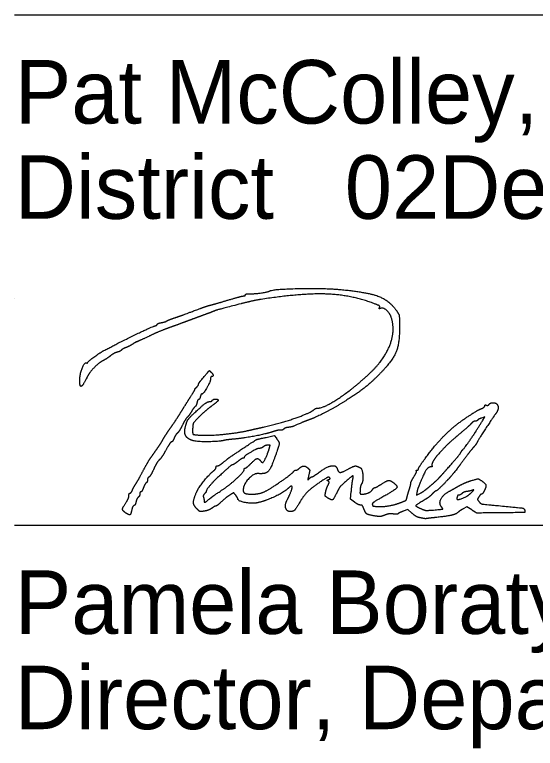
# Model space of a CAD drawing. Extents: x 0 to 34, y 0 to 22.
# Drawn here: x 24.5 to 25.648, y 7.199 to 8.816 of the extents above; entities that cross this region are included whole.
import ezdxf

# ---------------------------------------------------------------- set-up
doc = ezdxf.new("R2010")
doc.units = 0
doc.layers.add('SH_Data', color=7, linetype='Continuous')
doc.layers.add('SH_Text', color=7, linetype='Continuous')

msp = doc.modelspace()

# ---------------------------------------------------------------- linework, layer by layer
at = {"layer": 'SH_Data'}
for p, q in [((24.5, 8.816), (28, 8.816)), ((24.5, 8.191), (24.5, 8.191)), ((24.5, 7.691), (28, 7.691))]:
    msp.add_line(p, q, dxfattribs=at)
at = {"layer": 'SH_Text'}
for points in [[(25.5318, 7.9205), (25.5372, 7.9294), (25.5298, 7.9268)], [(25.0545, 7.8843), (25.0725, 7.8883), (25.0772, 7.8822)], [(25.2494, 7.7415), (25.2411, 7.7478), (25.2426, 7.7649)], [(25.3874, 7.7635), (25.3864, 7.757), (25.3951, 7.7614)], [(25.5083, 7.7242), (25.4976, 7.731), (25.4892, 7.7264)], [(25.3764, 7.7172), (25.3672, 7.7254), (25.3567, 7.7214)]]:
    msp.add_lwpolyline(points, dxfattribs=at)
for points in [[(25.0089, 8.1984), (25.0089, 8.1998), (25.0129, 8.2008), (25.0179, 8.2007)], [(25.0179, 8.2007), (25.0275, 8.2004), (25.0585, 8.2047), (25.0619, 8.2069)], [(25.2926, 8.1792), (25.242, 8.1982), (25.1341, 8.2022), (25.0437, 8.1884)], [(25.0619, 8.2069), (25.0687, 8.2111), (25.1857, 8.2134), (25.2201, 8.21)], [(25.2201, 8.21), (25.2794, 8.2041), (25.3269, 8.1858), (25.3427, 8.1628)], [(24.9333, 8.1761), (24.9386, 8.1775), (24.9561, 8.1825), (24.9721, 8.1873)], [(24.9721, 8.1873), (24.9882, 8.192), (25.0031, 8.1959), (25.0051, 8.1959)], [(25.0437, 8.1884), (25.0345, 8.187), (25.0145, 8.1827), (24.9993, 8.1787)], [(25.0051, 8.1959), (25.0072, 8.1959), (25.0089, 8.1971), (25.0089, 8.1984)], [(24.8529, 8.1477), (24.8676, 8.1528), (24.8741, 8.1552), (24.9093, 8.1683)], [(24.9093, 8.1683), (24.9172, 8.1713), (24.928, 8.1748), (24.9333, 8.1761)], [(24.9993, 8.1787), (24.9483, 8.1655), (24.944, 8.1643), (24.9333, 8.1599)], [(25.3049, 8.1706), (25.3059, 8.1731), (25.3024, 8.1755), (25.2926, 8.1792)], [(25.3073, 8.1685), (25.3047, 8.1675), (25.304, 8.1682), (25.3049, 8.1706)], [(25.3307, 8.1486), (25.3274, 8.1584), (25.313, 8.1707), (25.3073, 8.1685)], [(24.9105, 8.1515), (24.9006, 8.1479), (24.8855, 8.1423), (24.8769, 8.1391)], [(24.9333, 8.1599), (24.9307, 8.1589), (24.9204, 8.1551), (24.9105, 8.1515)], [(25.3427, 8.1628), (25.3476, 8.1555), (25.3486, 8.1512), (25.3489, 8.1333)], [(24.8145, 8.1334), (24.8145, 8.1345), (24.8185, 8.1362), (24.8235, 8.1371)], [(24.8235, 8.1371), (24.8284, 8.138), (24.8336, 8.1396), (24.8349, 8.1405)], [(24.8349, 8.1405), (24.8362, 8.1415), (24.8443, 8.1448), (24.8529, 8.1477)], [(24.8769, 8.1391), (24.8683, 8.1358), (24.8521, 8.1299), (24.8409, 8.1259)], [(25.2852, 8.0274), (25.3161, 8.0568), (25.34, 8.1204), (25.3307, 8.1486)], [(24.6969, 8.0755), (24.7271, 8.0918), (24.8007, 8.1274), (24.8091, 8.1299)], [(24.8409, 8.1259), (24.8297, 8.1219), (24.8093, 8.1134), (24.7957, 8.1069)], [(24.8091, 8.1299), (24.8121, 8.1308), (24.8145, 8.1324), (24.8145, 8.1334)], [(25.3489, 8.1333), (25.3496, 8.0926), (25.3335, 8.0529), (25.3041, 8.023)], [(24.7957, 8.1069), (24.782, 8.1004), (24.7704, 8.0951), (24.7698, 8.0951)], [(24.7598, 8.0895), (24.7549, 8.0864), (24.7482, 8.083), (24.745, 8.082)], [(24.7698, 8.0951), (24.7693, 8.0951), (24.7648, 8.0926), (24.7598, 8.0895)], [(24.6609, 8.0489), (24.6609, 8.0511), (24.6863, 8.0698), (24.6969, 8.0755)], [(24.7261, 8.072), (24.7226, 8.0711), (24.7159, 8.0675), (24.7113, 8.0639)], [(24.7358, 8.0768), (24.734, 8.075), (24.7297, 8.0728), (24.7261, 8.072)], [(24.745, 8.082), (24.7418, 8.0809), (24.7376, 8.0786), (24.7358, 8.0768)], [(24.7113, 8.0639), (24.7067, 8.0603), (24.6995, 8.0557), (24.6954, 8.0536)], [(24.6437, 8.0111), (24.6438, 8.0242), (24.6545, 8.0508), (24.6586, 8.0483)], [(24.6586, 8.0483), (24.6599, 8.0475), (24.6609, 8.0478), (24.6609, 8.0489)], [(24.6954, 8.0536), (24.685, 8.0482), (24.6651, 8.0274), (24.6589, 8.0153)], [(24.9111, 8.01), (24.9296, 8.0321), (24.9289, 8.0316), (24.933, 8.0282)], [(24.933, 8.0282), (24.9373, 8.0246), (24.9382, 8.0183), (24.9345, 8.0183)], [(25.1685, 7.9487), (25.1826, 7.9487), (25.2507, 7.9946), (25.2852, 8.0274)], [(25.3041, 8.023), (25.2855, 8.0041), (25.2531, 7.9792), (25.2226, 7.9603)], [(24.6451, 7.9973), (24.6443, 7.9981), (24.6437, 8.0043), (24.6437, 8.0111)], [(24.6589, 8.0153), (24.6522, 8.0024), (24.6469, 7.9955), (24.6451, 7.9973)], [(24.9057, 8.0013), (24.9057, 8.0025), (24.9081, 8.0064), (24.9111, 8.01)], [(24.9321, 8.0133), (24.9321, 8.0077), (24.9162, 7.9799), (24.913, 7.9799)], [(24.9345, 8.0183), (24.9332, 8.0183), (24.9321, 8.0161), (24.9321, 8.0133)], [(24.8881, 7.9739), (24.8937, 7.9825), (24.8977, 7.9895), (24.8971, 7.9895)], [(24.8971, 7.9895), (24.8966, 7.9895), (24.8983, 7.9917), (24.9009, 7.9943)], [(24.9009, 7.9943), (24.9035, 7.997), (24.9057, 8.0001), (24.9057, 8.0013)], [(24.8661, 7.9389), (24.8727, 7.9495), (24.8826, 7.9653), (24.8881, 7.9739)], [(24.9095, 7.9739), (24.9087, 7.9706), (24.907, 7.9679), (24.9058, 7.9679)], [(24.913, 7.9799), (24.9119, 7.9799), (24.9103, 7.9772), (24.9095, 7.9739)], [(24.8973, 7.939), (24.913, 7.9536), (24.9258, 7.9631), (24.9297, 7.9631)], [(24.9021, 7.9608), (24.9012, 7.9568), (24.8995, 7.953), (24.8982, 7.9522)], [(24.9058, 7.9679), (24.9047, 7.9679), (24.903, 7.9647), (24.9021, 7.9608)], [(24.9297, 7.9631), (24.9322, 7.9631), (24.9349, 7.9642), (24.9357, 7.9655)], [(24.9489, 7.9659), (24.9489, 7.9648), (24.9421, 7.9589), (24.9339, 7.9528)], [(24.9357, 7.9655), (24.9375, 7.9684), (24.9489, 7.9688), (24.9489, 7.9659)], [(25.2226, 7.9603), (25.2035, 7.9485), (25.1622, 7.9275), (25.1481, 7.9224)], [(25.5403, 7.9551), (25.5422, 7.9544), (25.545, 7.9554), (25.5466, 7.9573)], [(25.5466, 7.9573), (25.5482, 7.9592), (25.5519, 7.9607), (25.5548, 7.9607)], [(25.5548, 7.9607), (25.5643, 7.9607), (25.568, 7.9447), (25.5606, 7.9357)], [(24.8897, 7.9407), (24.8863, 7.9352), (24.8822, 7.9296), (24.8806, 7.9283)], [(24.8982, 7.9522), (24.8969, 7.9514), (24.8931, 7.9462), (24.8897, 7.9407)], [(24.9339, 7.9528), (24.9256, 7.9467), (24.9131, 7.9358), (24.9061, 7.9287)], [(25.0485, 7.9068), (25.0854, 7.915), (25.1517, 7.9379), (25.1603, 7.9454)], [(25.1603, 7.9454), (25.1624, 7.9472), (25.1661, 7.9487), (25.1685, 7.9487)], [(25.5001, 7.9304), (25.5191, 7.9426), (25.5209, 7.9437), (25.5291, 7.9474)], [(25.5291, 7.9474), (25.5334, 7.9493), (25.5369, 7.9521), (25.5369, 7.9537)], [(25.5369, 7.9537), (25.5369, 7.9552), (25.5384, 7.9559), (25.5403, 7.9551)], [(24.8443, 7.9059), (24.8497, 7.9134), (24.8595, 7.9282), (24.8661, 7.9389)], [(24.8806, 7.9283), (24.8789, 7.927), (24.8742, 7.9194), (24.8702, 7.9114)], [(24.876, 7.9043), (24.8787, 7.9174), (24.8849, 7.9274), (24.8973, 7.939)], [(24.9061, 7.9287), (24.8954, 7.9177), (24.8932, 7.914), (24.8927, 7.9058)], [(25.4055, 7.8378), (25.4278, 7.8686), (25.4728, 7.9127), (25.5001, 7.9304)], [(25.5606, 7.9357), (25.5564, 7.9307), (25.5236, 7.8802), (25.5204, 7.8741)], [(25.5298, 7.9268), (25.5258, 7.9254), (25.5219, 7.9233), (25.5212, 7.9221)], [(24.8702, 7.9114), (24.8662, 7.9034), (24.8611, 7.8954), (24.859, 7.8936)], [(25.1325, 7.9162), (25.1154, 7.9088), (25.1105, 7.9071), (25.1039, 7.9063)], [(25.1481, 7.9224), (25.1435, 7.9207), (25.1364, 7.918), (25.1325, 7.9162)], [(25.507, 7.9145), (25.5043, 7.9116), (25.4918, 7.9005), (25.4793, 7.89)], [(25.489, 7.8575), (25.4918, 7.8595), (25.52, 7.901), (25.5318, 7.9205)], [(25.5158, 7.9199), (25.5136, 7.9199), (25.5097, 7.9175), (25.507, 7.9145)], [(25.5212, 7.9221), (25.5204, 7.9209), (25.518, 7.9199), (25.5158, 7.9199)], [(24.8276, 7.8803), (24.8315, 7.8869), (24.839, 7.8985), (24.8443, 7.9059)], [(24.859, 7.8936), (24.8568, 7.8918), (24.8535, 7.8867), (24.8517, 7.8823)], [(24.8913, 7.8775), (24.8809, 7.8814), (24.8737, 7.8938), (24.876, 7.9043)], [(24.8927, 7.9058), (24.8918, 7.8923), (24.8959, 7.8895), (24.9165, 7.8889)], [(24.9165, 7.8889), (24.9358, 7.8884), (24.9936, 7.8945), (25.0149, 7.8993)], [(25.0683, 7.8963), (25.0518, 7.891), (25.0067, 7.8826), (24.9829, 7.8803)], [(25.0149, 7.8993), (25.0228, 7.9011), (25.0379, 7.9045), (25.0485, 7.9068)], [(25.0863, 7.9001), (25.0846, 7.9007), (25.0765, 7.899), (25.0683, 7.8963)], [(25.0931, 7.9022), (25.091, 7.9004), (25.0879, 7.8995), (25.0863, 7.9001)], [(25.1039, 7.9063), (25.1, 7.9059), (25.0952, 7.9041), (25.0931, 7.9022)], [(24.8146, 7.8597), (24.8179, 7.8645), (24.8238, 7.8737), (24.8276, 7.8803)], [(24.8517, 7.8823), (24.8498, 7.8779), (24.8473, 7.8743), (24.846, 7.8743)], [(24.9625, 7.8776), (24.9488, 7.8746), (24.8993, 7.8745), (24.8913, 7.8775)], [(24.9829, 7.8803), (24.9746, 7.8795), (24.9654, 7.8783), (24.9625, 7.8776)], [(25.0005, 7.8579), (25.0322, 7.8789), (25.0335, 7.8796), (25.0545, 7.8843)], [(25.0772, 7.8822), (25.0838, 7.8734), (25.0836, 7.8685), (25.0759, 7.846)], [(25.4793, 7.89), (25.4597, 7.8734), (25.448, 7.862), (25.4313, 7.8432)], [(24.846, 7.8743), (24.8447, 7.8743), (24.8393, 7.8664), (24.8339, 7.8568)], [(25.0399, 7.8599), (25.0377, 7.8599), (25.0333, 7.8585), (25.0302, 7.8568)], [(25.0486, 7.8635), (25.0461, 7.8615), (25.0421, 7.8599), (25.0399, 7.8599)], [(25.0471, 7.8287), (25.0489, 7.8287), (25.0587, 7.8499), (25.0618, 7.8605)], [(25.0585, 7.8671), (25.0557, 7.867), (25.0512, 7.8654), (25.0486, 7.8635)], [(25.0618, 7.8605), (25.0635, 7.8663), (25.0631, 7.8671), (25.0585, 7.8671)], [(25.5118, 7.8619), (25.5088, 7.8587), (25.4999, 7.8474), (25.492, 7.8367)], [(25.5204, 7.8741), (25.5187, 7.8706), (25.5148, 7.8652), (25.5118, 7.8619)], [(24.801, 7.8405), (24.8051, 7.8463), (24.8112, 7.8549), (24.8146, 7.8597)], [(24.8339, 7.8568), (24.8286, 7.8471), (24.8219, 7.8371), (24.8191, 7.8346)], [(24.9613, 7.83), (24.975, 7.841), (24.973, 7.8396), (25.0005, 7.8579)], [(25.0302, 7.8568), (25.0158, 7.8489), (25.0065, 7.8425), (25.0065, 7.8405)], [(25.0759, 7.846), (25.0656, 7.8161), (25.0537, 7.803), (25.0377, 7.8044)], [(25.4538, 7.8146), (25.4691, 7.8317), (25.4827, 7.8481), (25.4851, 7.8524)], [(25.4851, 7.8524), (25.4863, 7.8546), (25.4881, 7.8569), (25.489, 7.8575)], [(24.7821, 7.8083), (24.7884, 7.8202), (24.7969, 7.8347), (24.801, 7.8405)], [(24.8191, 7.8346), (24.8162, 7.832), (24.8107, 7.8229), (24.8068, 7.8143)], [(24.9475, 7.8215), (24.9493, 7.8215), (24.9555, 7.8253), (24.9613, 7.83)], [(24.9921, 7.8311), (24.9871, 7.8272), (24.9821, 7.8239), (24.981, 7.8239)], [(25.0038, 7.8383), (25.0024, 7.8383), (24.9971, 7.8351), (24.9921, 7.8311)], [(25.0065, 7.8405), (25.0065, 7.8393), (25.0053, 7.8383), (25.0038, 7.8383)], [(25.0209, 7.8263), (25.031, 7.8365), (25.0376, 7.8383), (25.0425, 7.8323)], [(25.0425, 7.8323), (25.0441, 7.8304), (25.0462, 7.8287), (25.0471, 7.8287)], [(25.3905, 7.8145), (25.3905, 7.8159), (25.3972, 7.8264), (25.4055, 7.8378)], [(25.4313, 7.8432), (25.4255, 7.8366), (25.4192, 7.8237), (25.4206, 7.8213)], [(25.492, 7.8367), (25.4841, 7.8261), (25.4765, 7.8159), (25.475, 7.814)], [(24.8068, 7.8143), (24.8029, 7.8058), (24.7981, 7.7979), (24.7963, 7.7968)], [(24.9387, 7.8103), (24.9417, 7.8127), (24.9441, 7.8162), (24.9441, 7.8181)], [(24.9441, 7.8181), (24.9441, 7.82), (24.9456, 7.8215), (24.9475, 7.8215)], [(24.981, 7.8239), (24.9791, 7.8239), (24.9706, 7.8167), (24.9453, 7.7934)], [(24.9604, 7.7702), (24.976, 7.7806), (25.0065, 7.8093), (25.0065, 7.8136)], [(25.0065, 7.8136), (25.0065, 7.8153), (25.0076, 7.8167), (25.0089, 7.8167)], [(25.0089, 7.8167), (25.0102, 7.8167), (25.0156, 7.8211), (25.0209, 7.8263)], [(25.1152, 7.8089), (25.1163, 7.8106), (25.1186, 7.8119), (25.1204, 7.8119)], [(25.1204, 7.8119), (25.1223, 7.8119), (25.1255, 7.8137), (25.1277, 7.8158)], [(25.1277, 7.8158), (25.1326, 7.8208), (25.1426, 7.8209), (25.1475, 7.8159)], [(25.1475, 7.8159), (25.1507, 7.8128), (25.1509, 7.8103), (25.1488, 7.8011)], [(25.1657, 7.8033), (25.1859, 7.8184), (25.2086, 7.824), (25.2116, 7.8146)], [(25.2116, 7.8146), (25.214, 7.807), (25.2221, 7.8069), (25.2354, 7.8142)], [(25.2354, 7.8142), (25.2474, 7.8208), (25.2546, 7.8216), (25.2628, 7.817)], [(25.2628, 7.817), (25.2672, 7.8145), (25.2689, 7.7865), (25.265, 7.7813)], [(25.3863, 7.8105), (25.3855, 7.8113), (25.3862, 7.8119), (25.3877, 7.8119)], [(25.3877, 7.8119), (25.3892, 7.8119), (25.3905, 7.8131), (25.3905, 7.8145)], [(25.4184, 7.8191), (25.412, 7.8191), (25.4025, 7.804), (25.3904, 7.7747)], [(25.4206, 7.8213), (25.4214, 7.8201), (25.4204, 7.8191), (25.4184, 7.8191)], [(25.4382, 7.7971), (25.4413, 7.8006), (25.4484, 7.8085), (25.4538, 7.8146)], [(25.475, 7.814), (25.4617, 7.7976), (25.4572, 7.7925), (25.4453, 7.7803)], [(24.7667, 7.7807), (24.7689, 7.784), (24.7759, 7.7965), (24.7821, 7.8083)], [(24.7963, 7.7968), (24.7944, 7.7958), (24.7929, 7.7929), (24.7929, 7.7904)], [(24.9006, 7.7621), (24.9051, 7.7725), (24.9283, 7.802), (24.9387, 7.8103)], [(25.0377, 7.8044), (25.0273, 7.8053), (25.0041, 7.7799), (25.0041, 7.7676)], [(25.0725, 7.7771), (25.0911, 7.7894), (25.1135, 7.8061), (25.1152, 7.8089)], [(25.1488, 7.8011), (25.1465, 7.7909), (25.1466, 7.7904), (25.1504, 7.7939)], [(25.1504, 7.7939), (25.1526, 7.7959), (25.1553, 7.7975), (25.1562, 7.7975)], [(25.1562, 7.7975), (25.1572, 7.7975), (25.1615, 7.8001), (25.1657, 7.8033)], [(25.1943, 7.7955), (25.1925, 7.7973), (25.1866, 7.7945), (25.1741, 7.786)], [(25.1927, 7.7913), (25.1957, 7.7924), (25.1962, 7.7936), (25.1943, 7.7955)], [(25.2455, 7.7897), (25.2474, 7.7992), (25.2447, 7.7996), (25.2354, 7.7914)], [(25.3737, 7.7829), (25.3737, 7.7847), (25.3769, 7.7914), (25.3807, 7.7976)], [(25.3807, 7.7976), (25.3846, 7.8039), (25.3871, 7.8097), (25.3863, 7.8105)], [(25.4181, 7.7783), (25.426, 7.7851), (25.4351, 7.7936), (25.4382, 7.7971)], [(24.7598, 7.7681), (24.7614, 7.7718), (24.7645, 7.7774), (24.7667, 7.7807)], [(24.7904, 7.7843), (24.789, 7.7834), (24.7862, 7.7785), (24.7841, 7.7733)], [(24.7929, 7.7904), (24.7929, 7.7879), (24.7918, 7.7851), (24.7904, 7.7843)], [(24.9453, 7.7934), (24.9362, 7.785), (24.9225, 7.768), (24.9225, 7.765)], [(25.1741, 7.786), (25.1544, 7.7726), (25.1372, 7.7555), (25.1289, 7.7411)], [(25.1915, 7.7878), (25.1893, 7.7892), (25.1896, 7.7901), (25.1927, 7.7913)], [(25.1908, 7.778), (25.1937, 7.7842), (25.1938, 7.7864), (25.1915, 7.7878)], [(25.2354, 7.7914), (25.2195, 7.7774), (25.2158, 7.773), (25.2103, 7.7616)], [(25.2426, 7.7649), (25.2434, 7.7743), (25.2447, 7.7854), (25.2455, 7.7897)], [(25.265, 7.7813), (25.2637, 7.7797), (25.2624, 7.774), (25.262, 7.7687)], [(25.2945, 7.7735), (25.2957, 7.7735), (25.3018, 7.7768), (25.3081, 7.7807)], [(25.3363, 7.7837), (25.346, 7.7761), (25.3391, 7.7682), (25.3076, 7.7505)], [(25.3081, 7.7807), (25.321, 7.789), (25.3286, 7.7898), (25.3363, 7.7837)], [(25.3702, 7.7687), (25.3721, 7.7747), (25.3737, 7.781), (25.3737, 7.7829)], [(25.4453, 7.7803), (25.4378, 7.7726), (25.4308, 7.7663), (25.4297, 7.7663)], [(25.4781, 7.7763), (25.486, 7.7808), (25.4992, 7.7865), (25.5074, 7.789)], [(25.5074, 7.789), (25.5215, 7.7932), (25.5226, 7.7932), (25.5285, 7.7894)], [(25.5285, 7.7894), (25.5381, 7.7831), (25.5405, 7.7757), (25.5359, 7.7667)], [(24.7545, 7.7615), (24.7559, 7.7615), (24.7583, 7.7645), (24.7598, 7.7681)], [(24.7782, 7.7639), (24.7771, 7.7639), (24.7761, 7.7619), (24.7761, 7.7594)], [(24.7841, 7.7733), (24.7821, 7.7682), (24.7794, 7.7639), (24.7782, 7.7639)], [(24.9225, 7.765), (24.9225, 7.7642), (24.9208, 7.7619), (24.9188, 7.7599)], [(24.9289, 7.7478), (24.9364, 7.7539), (24.9417, 7.7576), (24.9604, 7.7702)], [(25.0041, 7.7676), (25.0041, 7.7625), (25.0119, 7.7591), (25.024, 7.7591)], [(25.024, 7.7591), (25.0371, 7.7591), (25.0562, 7.7662), (25.0725, 7.7771)], [(25.1045, 7.7729), (25.0949, 7.7638), (25.0562, 7.745), (25.0377, 7.7405)], [(25.1015, 7.7471), (25.1056, 7.7548), (25.1121, 7.7711), (25.1121, 7.7738)], [(25.1121, 7.7738), (25.1121, 7.7769), (25.1081, 7.7764), (25.1045, 7.7729)], [(25.1857, 7.7623), (25.1865, 7.7665), (25.1888, 7.7736), (25.1908, 7.778)], [(25.262, 7.7687), (25.2615, 7.7612), (25.2622, 7.7591), (25.2654, 7.7591)], [(25.2654, 7.7591), (25.2737, 7.7591), (25.2857, 7.764), (25.289, 7.7687)], [(25.289, 7.7687), (25.2908, 7.7713), (25.2933, 7.7735), (25.2945, 7.7735)], [(25.3654, 7.7517), (25.3661, 7.7551), (25.3683, 7.7628), (25.3702, 7.7687)], [(25.3904, 7.7747), (25.3893, 7.7721), (25.388, 7.767), (25.3874, 7.7635)], [(25.3951, 7.7614), (25.3998, 7.7639), (25.4102, 7.7715), (25.4181, 7.7783)], [(25.4297, 7.7663), (25.4286, 7.7663), (25.4247, 7.7632), (25.4211, 7.7594)], [(25.4415, 7.7309), (25.4354, 7.7383), (25.4452, 7.7581), (25.4585, 7.7653)], [(25.4585, 7.7653), (25.4614, 7.7668), (25.4702, 7.7718), (25.4781, 7.7763)], [(25.4975, 7.7649), (25.4936, 7.7644), (25.4887, 7.7623), (25.4865, 7.7603)], [(25.5093, 7.7676), (25.5067, 7.7666), (25.5013, 7.7654), (25.4975, 7.7649)], [(25.5069, 7.7621), (25.5124, 7.7676), (25.513, 7.769), (25.5093, 7.7676)], [(25.5359, 7.7667), (25.5337, 7.7625), (25.531, 7.7591), (25.5299, 7.7591)], [(24.7463, 7.7416), (24.7495, 7.7464), (24.7521, 7.7528), (24.7521, 7.7559)], [(24.7521, 7.7559), (24.7521, 7.759), (24.7532, 7.7615), (24.7545, 7.7615)], [(24.7727, 7.7521), (24.7708, 7.7505), (24.7685, 7.746), (24.7676, 7.742)], [(24.7761, 7.7594), (24.7761, 7.757), (24.7745, 7.7536), (24.7727, 7.7521)], [(24.9023, 7.7264), (24.8947, 7.734), (24.8941, 7.7468), (24.9006, 7.7621)], [(24.9188, 7.7599), (24.9167, 7.7578), (24.9156, 7.7546), (24.9164, 7.7526)], [(24.9164, 7.7526), (24.9171, 7.7507), (24.9177, 7.7476), (24.9177, 7.7457)], [(24.9177, 7.7457), (24.9177, 7.7409), (24.9211, 7.7415), (24.9289, 7.7478)], [(24.9762, 7.758), (24.968, 7.7526), (24.9654, 7.7506), (24.9542, 7.7405)], [(24.9875, 7.7566), (24.983, 7.7624), (24.983, 7.7624), (24.9762, 7.758)], [(24.992, 7.7492), (24.992, 7.75), (24.99, 7.7534), (24.9875, 7.7566)], [(25.0377, 7.7405), (25.0248, 7.7374), (24.9922, 7.7436), (24.992, 7.7492)], [(25.1082, 7.7207), (25.0998, 7.7207), (25.0958, 7.7365), (25.1015, 7.7471)], [(25.1903, 7.7508), (25.1853, 7.7541), (25.1845, 7.7561), (25.1857, 7.7623)], [(25.2103, 7.7616), (25.2036, 7.7479), (25.1988, 7.7453), (25.1903, 7.7508)], [(25.3076, 7.7505), (25.2943, 7.743), (25.2881, 7.7382), (25.289, 7.736)], [(25.3527, 7.741), (25.3615, 7.7444), (25.3645, 7.7469), (25.3654, 7.7517)], [(25.4211, 7.7594), (25.4175, 7.7556), (25.4094, 7.7494), (25.4031, 7.7458)], [(25.4755, 7.751), (25.473, 7.7445), (25.4984, 7.7534), (25.5069, 7.7621)], [(25.4769, 7.7557), (25.4769, 7.7552), (25.4763, 7.7531), (25.4755, 7.751)], [(25.4797, 7.7567), (25.4782, 7.7567), (25.4769, 7.7563), (25.4769, 7.7557)], [(25.4865, 7.7603), (25.4843, 7.7584), (25.4813, 7.7567), (25.4797, 7.7567)], [(25.524, 7.7533), (25.5205, 7.748), (25.5206, 7.7471), (25.5244, 7.7424)], [(25.5299, 7.7591), (25.5288, 7.7591), (25.5261, 7.7565), (25.524, 7.7533)], [(24.7446, 7.7179), (24.7376, 7.7228), (24.7381, 7.7295), (24.7463, 7.7416)], [(24.7629, 7.7336), (24.7612, 7.7329), (24.7591, 7.7288), (24.7583, 7.7244)], [(24.7676, 7.742), (24.7668, 7.7381), (24.7646, 7.7343), (24.7629, 7.7336)], [(24.9435, 7.7327), (24.9424, 7.7327), (24.9386, 7.7306), (24.935, 7.728)], [(24.9542, 7.7405), (24.9494, 7.7362), (24.9446, 7.7327), (24.9435, 7.7327)], [(25.1289, 7.7411), (25.1207, 7.727), (25.1143, 7.7207), (25.1082, 7.7207)], [(25.2624, 7.7351), (25.2599, 7.7351), (25.254, 7.738), (25.2494, 7.7415)], [(25.27, 7.7273), (25.2681, 7.7325), (25.2656, 7.7351), (25.2624, 7.7351)], [(25.289, 7.736), (25.2903, 7.7326), (25.291, 7.7324), (25.3029, 7.7317)], [(25.3029, 7.7317), (25.3134, 7.7311), (25.3396, 7.736), (25.3527, 7.741)], [(25.4031, 7.7458), (25.3852, 7.7354), (25.3842, 7.7321), (25.3971, 7.7266)], [(25.4239, 7.7241), (25.4434, 7.7257), (25.4452, 7.7264), (25.4415, 7.7309)], [(25.5244, 7.7424), (25.528, 7.7379), (25.533, 7.7368), (25.5669, 7.7337)], [(25.5669, 7.7337), (25.616, 7.7292), (25.6243, 7.7276), (25.6252, 7.7228)], [(24.7583, 7.7244), (24.7564, 7.7146), (24.7522, 7.7127), (24.7446, 7.7179)], [(24.9185, 7.7217), (24.9098, 7.7204), (24.9076, 7.721), (24.9023, 7.7264)], [(24.935, 7.728), (24.9314, 7.7254), (24.924, 7.7226), (24.9185, 7.7217)], [(25.2953, 7.7108), (25.2803, 7.7132), (25.2735, 7.7177), (25.27, 7.7273)], [(25.3353, 7.7153), (25.3295, 7.7161), (25.3222, 7.7151), (25.3164, 7.7128)], [(25.3454, 7.7156), (25.345, 7.7148), (25.3404, 7.7146), (25.3353, 7.7153)], [(25.3567, 7.7214), (25.3509, 7.7191), (25.3458, 7.7165), (25.3454, 7.7156)], [(25.391, 7.7077), (25.388, 7.7083), (25.3814, 7.7126), (25.3764, 7.7172)], [(25.3971, 7.7266), (25.4039, 7.7236), (25.4104, 7.723), (25.4239, 7.7241)], [(25.4775, 7.7186), (25.4738, 7.7149), (25.4523, 7.71), (25.4289, 7.7076)], [(25.4892, 7.7264), (25.4846, 7.724), (25.4794, 7.7204), (25.4775, 7.7186)], [(25.5549, 7.7177), (25.5192, 7.7174), (25.5188, 7.7174), (25.5083, 7.7242)], [(25.6252, 7.7228), (25.626, 7.7186), (25.624, 7.7185), (25.5549, 7.7177)], [(25.3164, 7.7128), (25.3094, 7.71), (25.3039, 7.7094), (25.2953, 7.7108)], [(25.4013, 7.7055), (25.3987, 7.7061), (25.394, 7.7071), (25.391, 7.7077)], [(25.4097, 7.7053), (25.4077, 7.7049), (25.4039, 7.705), (25.4013, 7.7055)], [(25.4289, 7.7076), (25.4203, 7.7067), (25.4117, 7.7057), (25.4097, 7.7053)]]:
    msp.add_open_spline(points, degree=2, dxfattribs=at)

# ---------------------------------------------------------------- texts
for s, p in [('Pat McColley, P.E., S.I.', (24.5, 8.576)), ('District       Deputy Director', (24.5, 8.366)), ('              02', (24.5, 8.366)), ('Pamela Boratyn', (24.5, 7.451)), ('Director, Department of Transportation', (24.5, 7.241))]:
    msp.add_text(s, height=0.14, dxfattribs=at).set_placement(p)

doc.saveas('drawing.dxf')
